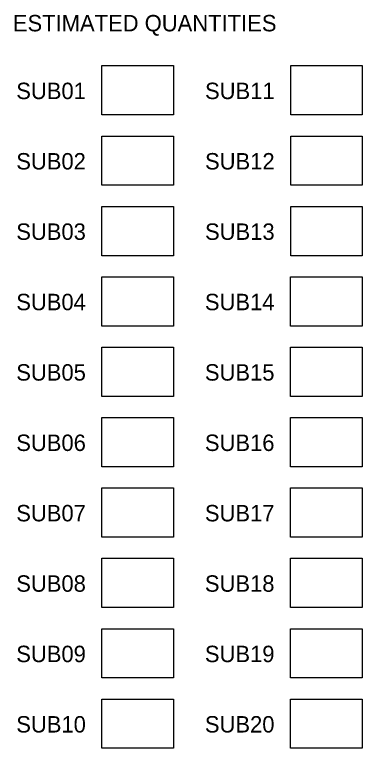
# Model space of a CAD drawing. Extents: x -542 to 295, y -281 to 32.
# Drawn here: x 146.4 to 294.6, y -280.6 to 32.1 of the extents above; entities that cross this region are included whole.
import ezdxf

# ---------------------------------------------------------------- set-up
doc = ezdxf.new("R2010")
doc.units = 0
doc.layers.add('Default', color=7, linetype='Continuous')
doc.layers.add('SC_Scratch1', color=7, linetype='Continuous')

msp = doc.modelspace()

# ---------------------------------------------------------------- linework, layer by layer
at = {"layer": 'Default'}
msp.add_lwpolyline([(183.64, -259.59), (214.14, -259.59), (214.14, -280.59), (183.64, -280.59)], close=True, dxfattribs=at)
at = {"layer": 'SC_Scratch1'}
for points in [[(183.64, 10.41), (214.14, 10.41), (214.14, -10.59), (183.64, -10.59)], [(264.08, 10.41), (294.58, 10.41), (294.58, -10.59), (264.08, -10.59)], [(183.64, -19.59), (214.14, -19.59), (214.14, -40.59), (183.64, -40.59)], [(264.08, -19.59), (294.58, -19.59), (294.58, -40.59), (264.08, -40.59)], [(183.64, -49.59), (214.14, -49.59), (214.14, -70.59), (183.64, -70.59)], [(264.08, -49.59), (294.58, -49.59), (294.58, -70.59), (264.08, -70.59)], [(183.58, -79.59), (214.08, -79.59), (214.08, -100.59), (183.58, -100.59)], [(264.02, -79.59), (294.52, -79.59), (294.52, -100.59), (264.02, -100.59)], [(183.64, -109.59), (214.14, -109.59), (214.14, -130.59), (183.64, -130.59)], [(264.02, -109.59), (294.52, -109.59), (294.52, -130.59), (264.02, -130.59)], [(183.64, -139.59), (214.14, -139.59), (214.14, -160.59), (183.64, -160.59)], [(264.02, -139.59), (294.52, -139.59), (294.52, -160.59), (264.02, -160.59)], [(183.64, -169.59), (214.14, -169.59), (214.14, -190.59), (183.64, -190.59)], [(264.02, -169.59), (294.52, -169.59), (294.52, -190.59), (264.02, -190.59)], [(183.64, -199.59), (214.14, -199.59), (214.14, -220.59), (183.64, -220.59)], [(264.02, -199.59), (294.52, -199.59), (294.52, -220.59), (264.02, -220.59)], [(183.64, -229.59), (214.14, -229.59), (214.14, -250.59), (183.64, -250.59)], [(264.02, -229.59), (294.52, -229.59), (294.52, -250.59), (264.02, -250.59)], [(264.02, -259.59), (294.52, -259.59), (294.52, -280.59), (264.02, -280.59)]]:
    msp.add_lwpolyline(points, close=True, dxfattribs=at)

# ---------------------------------------------------------------- texts
at = {"layer": 'Default'}
for s, p in [('ESTIMATED QUANTITIES', (145.66, 25.03)), ('SUB01', (147.11, -3.85)), ('SUB11', (227.55, -3.85)), ('SUB02', (147.11, -33.85)), ('SUB12', (227.55, -33.85)), ('SUB03', (147.11, -63.85)), ('SUB13', (227.55, -63.85)), ('SUB04', (147.11, -93.85)), ('SUB14', (227.49, -93.85)), ('SUB05', (147.11, -123.85)), ('SUB15', (227.49, -123.85)), ('SUB06', (147.11, -153.85)), ('SUB16', (227.49, -153.85)), ('SUB07', (147.11, -183.85)), ('SUB17', (227.49, -183.85)), ('SUB08', (147.11, -213.85)), ('SUB18', (227.49, -213.85)), ('SUB09', (147.11, -243.85)), ('SUB19', (227.49, -243.85)), ('SUB10', (147.11, -273.85)), ('SUB20', (227.49, -273.85))]:
    msp.add_text(s, height=7, dxfattribs=at).set_placement(p)

doc.saveas('drawing.dxf')
